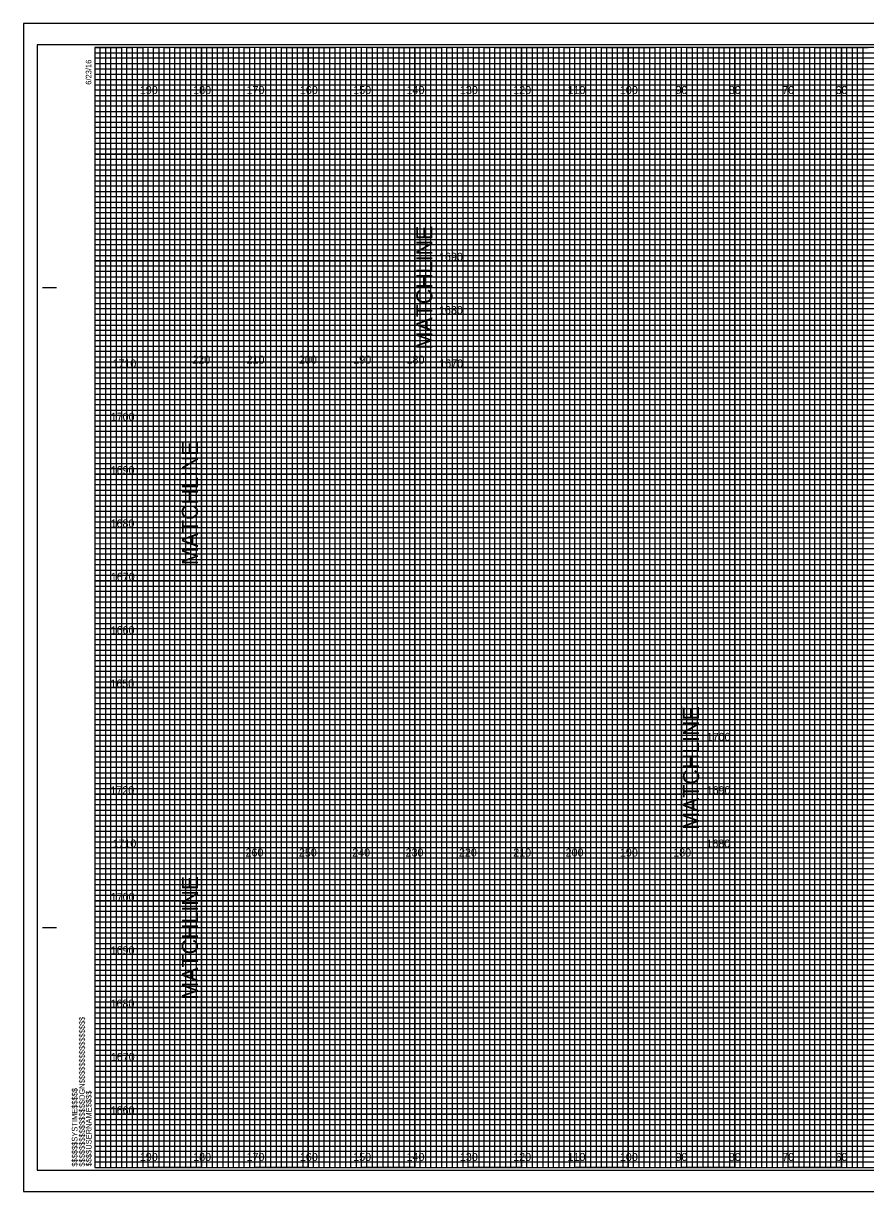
# Model space of a CAD drawing. Extents: x -13 to 323, y -5 to 6154.
# Drawn here: x -13.4 to 144.5, y 215.5 to 434.5 of the extents above; entities that cross this region are included whole.
import ezdxf

# ---------------------------------------------------------------- set-up
doc = ezdxf.new("R2010")
doc.units = 0
for name, color, linetype in [('Old_Level_62', 7, 'Continuous'), ('Pattern 4', 7, 'Continuous'), ('Prop Retaining Wall', 7, 'Continuous'), ('Prop XS Alignment Label', 7, 'Continuous'), ('Prop XS DDE', 7, 'Continuous'), ('Prop XS DDE Elevations', 7, 'Continuous'), ('Prop XS DDE Slope Text', 7, 'Continuous'), ('Prop XS Earthwork Shape', 7, 'Continuous'), ('Prop XS Elevation Labels', 7, 'Continuous'), ('Prop XS Station Labels', 7, 'Continuous'), ('Raster_Level_0', 7, 'Continuous'), ('Scratch_Level_3', 7, 'Continuous'), ('Sheet Cutting Line CELL', 7, 'Continuous')]:
    doc.layers.add(name, color=color, linetype=linetype)

msp = doc.modelspace()

# ---------------------------------------------------------------- linework, layer by layer
at = {"layer": 'Pattern 4'}
for p, q in [((60, 396.59), (60, 371.59)), ((20, 356.15), (20, 331.15)), ((110, 306.52), (110, 281.52)), ((20, 274.7), (20, 249.7))]:
    msp.add_line(p, q, dxfattribs=at)
at = {"layer": 'Prop Retaining Wall'}
for p, q in [((0, 429), (260, 429)), ((260, 427.98), (0, 427.98)), ((0, 427.98), (0, 427)), ((0, 427), (260, 427)), ((260, 425.89), (0, 425.89)), ((0, 425.89), (0, 424)), ((0, 424), (320, 424))]:
    msp.add_line(p, q, dxfattribs=at)
for points in [[(0, 423), (270, 423), (320, 423), (320, 422), (0, 422)], [(0, 421), (320, 421), (320, 419), (0, 419)], [(0, 418), (320, 418), (320, 417), (0, 416.98)], [(0, 416), (320, 416), (320, 414), (0, 414)], [(0, 413), (320, 413), (320, 412), (0, 412)], [(0, 411), (320, 411), (320, 409), (0, 409)], [(0, 408), (320, 408), (320, 407), (0, 407)], [(0, 406), (320, 406), (320, 404), (0, 404)], [(0, 403), (320, 403), (320, 402), (0, 402)], [(0, 401), (320, 401), (320, 399), (0, 399)], [(0, 398), (320, 398), (320, 397), (0, 397)], [(0, 396), (320, 396), (320, 393.95), (320, 393), (320, 392), (0, 392)], [(0, 394), (320, 394), (320, 393), (0, 393)], [(0, 391), (320, 391), (320, 389), (0, 389.03)], [(0, 389.03), (320, 389), (320, 388), (0, 388)], [(0, 387), (320, 387), (320, 386), (0, 386)], [(0, 384), (320, 384), (320, 383), (0, 383)], [(0, 382), (320, 382), (320, 381), (0, 381)], [(-0.07, 378.89), (320, 378.89), (320, 377.88), (-0.07, 377.88)], [(0, 377), (320, 377), (320, 376), (0, 376)], [(0, 374), (320, 374), (320, 373), (0, 373)], [(0, 372), (320, 372), (320, 371), (0, 371)], [(0, 369), (320, 369), (320, 368), (0, 368)], [(0, 367), (320, 367), (320, 366), (0, 366)], [(0, 364), (320, 364), (320, 363), (0, 363)], [(0, 362), (320, 362), (320, 361), (0, 361)], [(0, 359), (320, 359), (319.99, 357.98), (0, 358)], [(0, 357), (320, 357), (320, 356), (0, 356)], [(0, 354), (320, 354), (320, 353), (0, 353)], [(0, 352), (320, 352), (320, 351), (0, 351)], [(0, 349), (320, 349), (320, 348), (0, 348)], [(0, 347), (320, 347), (320, 346), (0, 346)], [(0, 344), (320, 344), (320, 343), (0, 343)], [(0, 342), (320, 342), (320, 341), (0, 341)], [(0, 339), (320, 339), (320, 338), (0, 338)], [(0, 336.99), (320.07, 336.91), (320, 336), (0, 336)], [(0, 334), (320, 334), (320, 333), (0, 333)], [(0, 332), (320, 332), (320, 331), (0, 331)], [(0, 329), (320, 329), (320, 328), (0, 328)], [(0, 327), (320, 327), (320, 326), (0, 326)], [(0, 324), (320, 324), (320, 323), (0, 323)], [(0, 322), (320, 322), (320, 321), (0, 321)], [(0, 319), (320, 319), (320, 318), (0, 318)], [(0, 317), (320, 317), (320, 316), (0, 316)], [(0, 314), (320, 314), (320, 313), (0, 313)], [(0, 312), (320, 312), (320, 311), (0, 311)], [(0, 309), (320, 309), (320, 308), (0, 308)], [(0, 307), (320, 307), (320, 306), (0, 306)], [(0, 304), (320, 304), (320, 303), (0, 303)], [(0, 302), (320, 302), (320, 301), (0, 301)], [(0, 299), (320, 299), (319.99, 297.98), (0, 298)], [(0, 297), (320, 297), (320, 296), (0, 296)], [(0, 294), (320, 294), (320, 293), (0, 293)], [(0, 292), (320, 292), (320, 291), (0, 291)], [(0, 289), (320, 289), (320, 288), (0, 288)], [(0, 287), (320, 287), (320, 286), (0, 286)], [(0, 284), (320, 284), (320, 283), (0, 283)], [(0, 282), (320, 282), (320, 281), (0, 281)], [(0, 279), (320, 279), (320, 278), (0, 278)], [(0, 276.99), (320.07, 276.91), (320, 276), (0, 276)], [(0, 274), (320, 274), (320, 273), (0, 273)], [(0, 272), (320, 272), (320, 271), (0, 271)], [(0, 269), (320, 269), (320, 268), (0, 268)], [(0, 267), (320, 267), (320, 266), (0, 266)], [(0, 264), (320, 264), (320, 263), (0, 263)], [(0, 262), (320, 262), (320, 261), (0, 261)], [(0, 259), (320, 259), (320, 258), (0, 258)], [(0, 257), (320, 257), (320, 256), (0, 256)], [(0, 254), (320, 254), (320, 253), (0, 253)], [(0, 252), (320, 252), (320, 251), (0, 251)], [(0, 249), (320, 249), (320, 248), (0, 248)], [(0, 247), (320, 247), (320, 246), (0, 246)], [(0, 244), (320, 244), (320, 243), (0, 243)], [(0, 242), (320, 242), (320, 241), (0, 241)], [(0, 239), (320, 239), (320, 238), (0, 238)], [(0, 237), (320, 237), (320, 236), (0, 236)], [(0, 234), (320, 234), (320, 233), (0, 233)], [(0, 232), (320, 232), (320, 231), (0, 231)], [(0, 229), (320, 229), (320, 228), (0, 228)], [(0, 227), (320, 227), (320, 226), (0, 226)], [(0, 224), (320, 224), (320, 223), (0, 223)], [(0, 222), (320, 222), (320, 221), (0, 221)]]:
    msp.add_lwpolyline(points, dxfattribs=at)
at = {"layer": 'Prop XS Alignment Label'}
for p, q in [((-9.8, 385), (-7.3, 385)), ((-9.7, 385), (-7.2, 385)), ((-9.8, 265), (-7.3, 265)), ((-9.7, 265), (-7.2, 265)), ((0, 220), (0, 220)), ((0, 220), (0, 220)), ((0, 220), (0, 220)), ((0, 220), (0, 220)), ((0, 220), (0, 220)), ((0, 220), (0, 220)), ((0, 220), (0, 220))]:
    msp.add_line(p, q, dxfattribs=at)
msp.add_lwpolyline([(320, 430), (0, 430), (0, 220), (320, 220)], close=True, dxfattribs=at)
at = {"layer": 'Prop XS DDE'}
msp.add_lwpolyline([(-13.4, 215.5), (323.3, 215.5), (323.3, 434.5), (-13.4, 434.5)], close=True, dxfattribs=at)
at = {"layer": 'Prop XS DDE Elevations'}
for p, q in [((10, 220), (10, 430)), ((20, 220), (20, 430)), ((30, 220), (30, 430)), ((40, 220), (40, 430)), ((50, 220), (50, 430)), ((60, 220), (60, 430)), ((70, 220), (70, 430)), ((80, 220), (80, 430)), ((90, 220), (90, 430)), ((100, 220), (100, 430)), ((110, 220), (110, 430)), ((120, 220), (120, 430)), ((130, 220), (130, 430)), ((140, 220), (140, 430)), ((0, 420), (320, 420)), ((0, 410), (320, 410)), ((0, 400), (320, 400)), ((0, 390), (320, 390)), ((0, 380), (320, 380)), ((0, 370), (320, 370)), ((0, 360), (320, 360)), ((0, 350), (320, 350)), ((0, 340), (320, 340)), ((0, 330), (320, 330)), ((0, 320), (320, 320)), ((0, 310), (320, 310)), ((0, 300), (320, 300)), ((0, 290), (320, 290)), ((0, 280), (320, 280)), ((0, 270), (320, 270)), ((0, 260), (320, 260)), ((0, 250), (320, 250)), ((0, 240), (320, 240)), ((0, 230), (320, 230))]:
    msp.add_line(p, q, dxfattribs=at)
at = {"layer": 'Prop XS DDE Slope Text'}
msp.add_lwpolyline([(-10.8, 219.5), (322.4, 219.5), (322.4, 430.5), (-10.8, 430.5)], close=True, dxfattribs=at)
at = {"layer": 'Prop XS Earthwork Shape'}
for p, q in [((10, 430), (0, 430)), ((10, 220), (10, 430)), ((30, 430), (20, 430)), ((20, 430), (20, 220)), ((30, 220), (30, 430)), ((50, 430), (40, 430)), ((40, 430), (40, 220)), ((50, 220), (50, 430)), ((70, 430), (60, 430)), ((60, 430), (60, 220)), ((70, 220), (70, 430)), ((90, 430), (80, 430)), ((80, 430), (80, 220)), ((90, 220), (90, 430)), ((110, 430), (100, 430)), ((100, 430), (100, 220)), ((110, 220), (110, 430)), ((130, 430), (120, 430)), ((120, 430), (120, 220)), ((130, 220), (130, 430)), ((150, 430), (140, 430)), ((140, 430), (140, 220)), ((20, 220), (10, 220)), ((40, 220), (30, 220)), ((60, 220), (50, 220)), ((80, 220), (70, 220)), ((100, 220), (90, 220)), ((120, 220), (110, 220)), ((140, 220), (130, 220))]:
    msp.add_line(p, q, dxfattribs=at)
for points in [[(0, 420), (320, 420), (320, 410), (0, 410)], [(0, 400), (320, 400), (320, 390), (0, 390)], [(0, 380), (320, 380), (320, 370), (0, 370)], [(0, 360), (320, 360), (320, 350), (0, 350)], [(0, 340), (320, 340), (320, 330), (0, 330)], [(0, 320), (320, 320), (320, 310), (0, 310)], [(0, 300), (320, 300), (320, 290), (0, 290)], [(0, 280), (320, 280), (320, 270), (0, 270)], [(0, 260), (320, 260), (320, 250), (0, 250)], [(0, 240), (320, 240), (320, 230), (0, 230)]]:
    msp.add_lwpolyline(points, dxfattribs=at)
at = {"layer": 'Prop XS Elevation Labels'}
for points in [[(0, 220), (1, 220), (1, 430), (2, 430), (2, 220)], [(2, 220), (3, 220), (3, 430), (4, 430), (4, 220)], [(5, 220), (6, 220), (6, 430), (7, 430), (7, 220)], [(7, 220), (8, 220), (8, 430), (9, 430), (9, 220)], [(10, 220), (11, 220), (11, 430), (12, 430), (12, 220)], [(12, 220), (13, 220), (13, 430), (14, 430), (14, 220)], [(15, 220), (16, 220), (16, 430), (17, 430), (17, 220)], [(17, 220), (18, 220), (18, 430), (19, 430), (19, 220)], [(20, 220), (21, 220), (21, 430), (22, 430), (22, 220)], [(22, 220), (23, 220), (23, 430), (24, 430), (24, 220)], [(25, 220), (26, 220), (26, 430), (27, 430), (27, 220)], [(27, 220), (28, 220), (28, 430), (29, 430), (29, 220)], [(30, 220), (31, 220), (31, 430), (32, 430), (32, 220)], [(32, 220), (33, 220), (33, 430), (34, 430), (34, 220)], [(35, 220), (36, 220), (36, 430), (37, 430), (37, 220)], [(37, 220), (38, 220), (38, 430), (39, 430), (39, 220)], [(40, 220), (41, 220), (41, 430), (42, 430), (42, 220)], [(42, 220), (43, 220), (43, 430), (44, 430), (44, 220)], [(45, 220), (46, 220), (46, 430), (47, 430), (47, 220)], [(47, 220), (48, 220), (48, 430), (49, 430), (49, 220)], [(50, 220), (51, 220), (51, 430), (52, 430), (52, 220)], [(52, 220), (53, 220), (53, 430), (54, 430), (54, 220)], [(55, 220), (56, 220), (56, 430), (57, 430), (57, 220)], [(57, 220), (58, 220), (58, 430), (59, 430), (59, 220)], [(60, 220), (61, 220), (61, 430), (62, 430), (62, 220)], [(62, 220), (63, 220), (63, 430), (64, 430), (64, 220)], [(65, 220), (66, 220), (66, 430), (67, 430), (67, 220)], [(67, 220), (68, 220), (68, 430), (69, 430), (69, 220)], [(70, 220), (71, 220), (71, 430), (72, 430), (72, 220)], [(72, 220), (73, 220), (73, 430), (74, 430), (74, 220)], [(75, 220), (76, 220), (76, 430), (77, 430), (77, 220)], [(77, 220), (78, 220), (78, 430), (79, 430), (79, 220)], [(80, 220), (81, 220), (81, 430), (82, 430), (82, 220)], [(82, 220), (83, 220), (83, 430), (84, 430), (84, 220)], [(85, 220), (86, 220), (86, 430), (87, 430), (87, 220)], [(87, 220), (88, 220), (88, 430), (89, 430), (89, 220)], [(90, 220), (91, 220), (91, 430), (92, 430), (92, 220)], [(92, 220), (93, 220), (93, 430), (94, 430), (94, 220)], [(95, 220), (96, 220), (96, 430), (97, 430), (97, 220)], [(97, 220), (98, 220), (98, 430), (99, 430), (99, 220)], [(100, 220), (101, 220), (101, 430), (102, 430), (102, 220)], [(102, 220), (103, 220), (103, 430), (104, 430), (104, 220)], [(105, 220), (106, 220), (106, 430), (107, 430), (107, 220)], [(107, 220), (108, 220), (108, 430), (109, 430), (109, 220)], [(110, 220), (111, 220), (111, 430), (112, 430), (112, 220)], [(112, 220), (113, 220), (113, 430), (114, 430), (114, 220)], [(115, 220), (116, 220), (116, 430), (117, 430), (117, 220)], [(117, 220), (118, 220), (118, 430), (119, 430), (119, 220)], [(120, 220), (121, 220), (121, 430), (122, 430), (122, 220)], [(122, 220), (123, 220), (123, 430), (124, 430), (124, 220)], [(125, 220), (126, 220), (126, 430), (127, 430), (127, 220)], [(127, 220), (128, 220), (128, 430), (129, 430), (129, 220)], [(130, 220), (131, 220), (131, 430), (132, 430), (132, 220)], [(132, 220), (133, 220), (133, 430), (134, 430), (134, 220)], [(135, 220), (136, 220), (136, 430), (137, 430), (137, 220)], [(137, 220), (138, 220), (138, 430), (139, 430), (139, 220)], [(140, 220), (141, 220), (141, 430), (142, 430), (142, 220)], [(142, 220), (143, 220), (143, 430), (144, 430), (144, 220)]]:
    msp.add_lwpolyline(points, dxfattribs=at)
at = {"layer": 'Prop XS Station Labels'}
for points in [[(0, 430), (5, 430), (5, 220), (15, 220), (15, 430), (25, 430), (25, 220), (35, 220), (35, 430), (45, 430), (45, 220), (55, 220), (55, 430), (65, 430), (65, 220), (75, 220), (75, 430), (85, 430), (85, 220), (95, 220), (95, 430), (105, 430), (105, 220), (115, 220), (115, 430), (125, 430), (125, 220), (135, 220), (135, 430), (145, 430)], [(0, 425), (275, 425)], [(0, 405), (320, 405), (320, 415), (0, 415)], [(0, 385), (320, 385), (320, 395), (0, 395)], [(0, 365), (320, 365), (320, 375), (0, 375)], [(0, 345), (320, 345), (320, 355), (0, 355)], [(0, 325), (320, 325), (320, 335), (0, 335)], [(0, 305), (320, 305), (320, 315), (0, 315)], [(0, 285), (320, 285), (320, 295), (0, 295)], [(0, 265), (320, 265), (320, 275), (0, 275)], [(0, 245), (320, 245), (320, 255), (0, 255)], [(0, 225), (320, 225), (320, 235), (0, 235)]]:
    msp.add_lwpolyline(points, dxfattribs=at)
at = {"layer": 'Sheet Cutting Line CELL'}
for p, q in [((323.3, 434.5), (-13.4, 434.5)), ((-13.4, 434.5), (-13.4, 215.5)), ((-13.4, 215.5), (323.3, 215.5))]:
    msp.add_line(p, q, dxfattribs=at)

# ---------------------------------------------------------------- texts
at = {"layer": 'Old_Level_62'}
for p in [(63.27, 373.39), (19.31, 332.95), (113.27, 283.32), (19.31, 251.5)]:
    msp.add_text('MATCHLINE', height=3, rotation=90, dxfattribs=at).set_placement(p)
at = {"layer": 'Prop XS Alignment Label'}
for s, p in [('6/23/16', (-0.65, 423)), ('$$$$$$$$$$$$$$$$DGN$$$$$$$$$$$$$$$$', (-1.88, 220.18)), ('$$$$$$SYSTIME$$$$$', (-3.26, 220.18)), ('$$$$USERNAME$$$$', (-0.62, 220.23))]:
    msp.add_text(s, height=1.05, rotation=90, dxfattribs=at).set_placement(p)
at = {"layer": 'Raster_Level_0'}
for s, p in [('190', (8.44, 421.25)), ('180', (18.44, 421.25)), ('170', (28.44, 421.25)), ('160', (38.44, 421.25)), ('150', (48.44, 421.25)), ('140', (58.44, 421.25)), ('130', (68.44, 421.25)), ('120', (78.44, 421.25)), ('110', (88.62, 421.25)), ('100', (98.44, 421.25)), ('90', (108.86, 421.25)), ('80', (118.86, 421.25)), ('70', (128.86, 421.25)), ('60', (138.86, 421.25)), ('220', (18.26, 370.71)), ('210', (28.44, 370.71)), ('200', (38.26, 370.71)), ('190', (48.44, 370.71)), ('180', (58.44, 370.71)), ('260', (28.26, 278.32)), ('250', (38.26, 278.32)), ('240', (48.26, 278.32)), ('230', (58.26, 278.32)), ('220', (68.26, 278.32)), ('210', (78.44, 278.32)), ('200', (88.26, 278.32)), ('190', (98.44, 278.32)), ('180', (108.44, 278.32)), ('190', (8.44, 221.25)), ('180', (18.44, 221.25)), ('170', (28.44, 221.25)), ('160', (38.44, 221.25)), ('150', (48.44, 221.25)), ('140', (58.44, 221.25)), ('130', (68.44, 221.25)), ('120', (78.44, 221.25)), ('110', (88.62, 221.25)), ('100', (98.44, 221.25)), ('90', (108.86, 221.25)), ('80', (118.86, 221.25)), ('70', (128.86, 221.25)), ('60', (138.86, 221.25))]:
    msp.add_text(s, height=1.5, dxfattribs=at).set_placement(p)
at = {"layer": 'Scratch_Level_3'}
for s, p in [('1690', (64.53, 390)), ('1680', (64.51, 380)), ('1710', (3.31, 370)), ('1670', (64.57, 370)), ('1700', (2.98, 360)), ('1690', (2.97, 350)), ('1680', (2.95, 340)), ('1670', (3, 330)), ('1660', (2.97, 320)), ('1650', (2.92, 310)), ('1700', (114.7, 300)), ('1720', (2.93, 290)), ('1690', (114.69, 290)), ('1710', (3.31, 280)), ('1680', (114.66, 280)), ('1700', (2.98, 270)), ('1690', (2.97, 260)), ('1680', (2.95, 250)), ('1670', (3, 240)), ('1660', (2.97, 230))]:
    msp.add_text(s, height=1.5, dxfattribs=at).set_placement(p)

doc.saveas('drawing.dxf')
